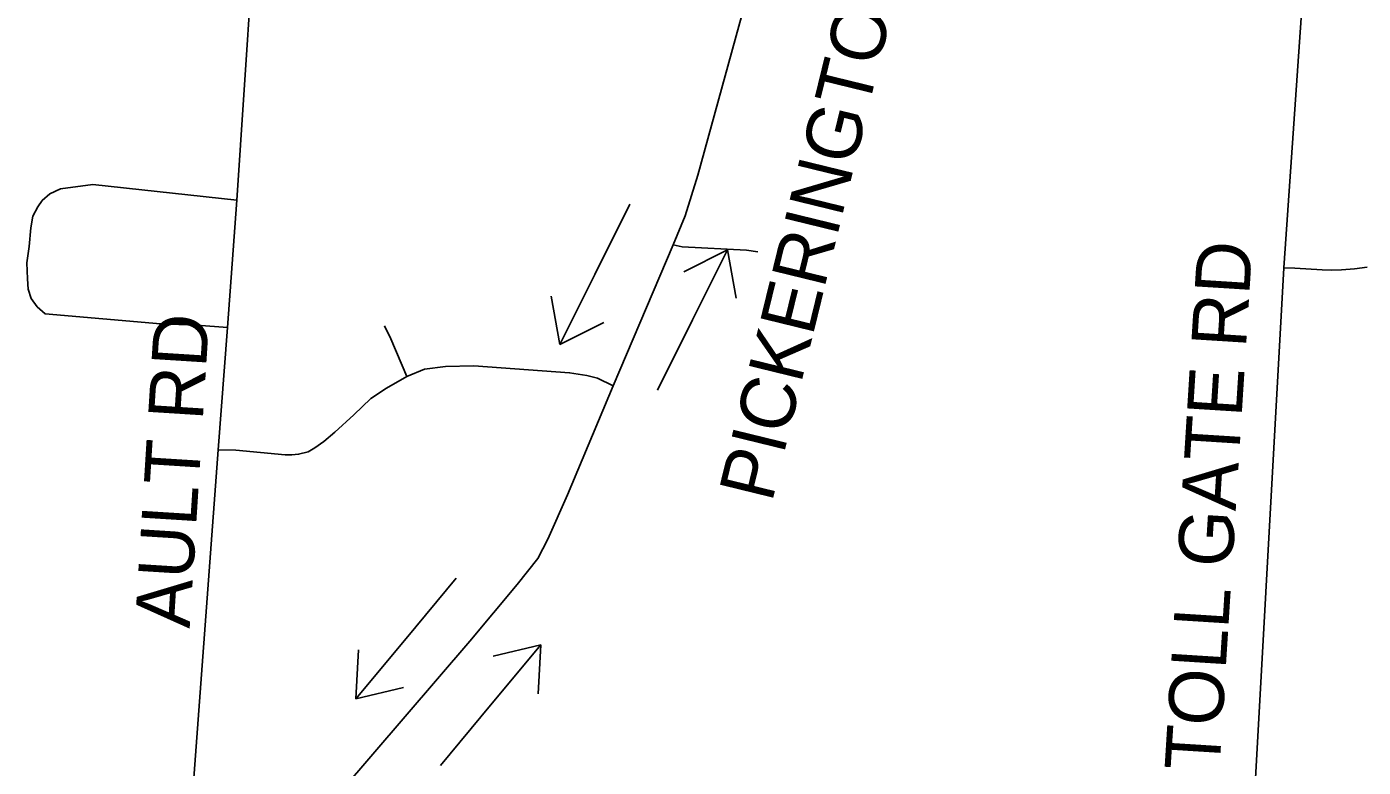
# Model space of a CAD drawing. Extents: x 1880545 to 1948545, y 79309 to 723051.
# Drawn here: x 1903722 to 1910544, y 696839 to 700619 of the extents above; entities that cross this region are included whole.
import ezdxf

# ---------------------------------------------------------------- set-up
doc = ezdxf.new("R2010")
doc.units = 0
for name, color, linetype in [('GM_X_County_Road', 7, 'Continuous'), ('GM_X_Township_Road', 7, 'Continuous'), ('SH_Text', 7, 'Continuous')]:
    doc.layers.add(name, color=color, linetype=linetype)

msp = doc.modelspace()

# ---------------------------------------------------------------- linework, layer by layer
at = {"layer": 'GM_X_County_Road'}
msp.add_lwpolyline([(1903743.6, 694852), (1904498.8, 695752), (1905984.5, 697482.2), (1906225.1, 697771.5), (1906330.5, 697904), (1906381.8, 698004.1), (1906482, 698229.9), (1906716.2, 698785.5), (1907022.1, 699505.3), (1907083, 699653.2), (1907147.2, 699860.4), (1907496.4, 701130), (1907579.5, 701447.1), (1907619.5, 701622.3), (1907630.8, 701703.2), (1907657.6, 701964), (1907699.4, 702415.6), (1907714.4, 702613)], dxfattribs=at)
at = {"layer": 'GM_X_Township_Road'}
for points in [[(1904498.8, 695752), (1904699.2, 698459.7), (1904747.1, 699083.9), (1904795.5, 699734.1), (1904909.4, 701450.1), (1904991.6, 702232.3), (1905034.1, 702803)], [(1909204, 694397.9), (1909237.3, 694606.7), (1909274.6, 694755.9), (1909351.4, 694905.3), (1909471.8, 695025), (1909703.6, 695238.2), (1909815.5, 695374.1), (1909874.1, 695504.6), (1909911.4, 695648.5), (1909954.1, 696077.5), (1910139.3, 699387.4), (1910347, 702406.2)], [(1903734.6, 699497.8), (1903743, 699591.9), (1903753.2, 699652), (1903779.5, 699699.9), (1903801.7, 699731.9), (1903839.9, 699765.8), (1903894.2, 699791.6), (1904059, 699813), (1904795.5, 699734.1)], [(1903734.6, 699497.8), (1903722.3, 699413.7), (1903726, 699331.6), (1903729.9, 699279.5), (1903745.7, 699231.3), (1903775.7, 699189.2), (1903815.6, 699152.9), (1904405.2, 699102.5), (1904589.7, 699095.8), (1904747.1, 699083.9)], [(1907022.1, 699505.3), (1907067.8, 699495.9), (1907396.8, 699478.5), (1907453.4, 699469.1)], [(1910139.3, 699387.4), (1910194.4, 699386), (1910334.6, 699377.2), (1910383.9, 699375.9), (1910433.1, 699377.5), (1910498.6, 699383.7), (1910563.9, 699390.9)], [(1905661.7, 698834.3), (1905581.5, 699025.7), (1905548.7, 699091.4)], [(1904699.2, 698459.7), (1904789.3, 698456.8), (1905042.1, 698434.2), (1905075.7, 698434), (1905109.9, 698436.9), (1905159.4, 698448.8), (1905193.3, 698469.6), (1905238.8, 698502.4), (1905295.3, 698549.8), (1905392, 698637.4), (1905479.4, 698721.2), (1905557.8, 698774.1), (1905661.7, 698834.3), (1905752.8, 698870.7), (1905860.4, 698885.3), (1906004.4, 698887.2), (1906492.9, 698852.5), (1906580.4, 698837.9), (1906635.1, 698825.2), (1906716.2, 698785.5)]]:
    msp.add_lwpolyline(points, dxfattribs=at)
at = {"layer": 'SH_Text'}
for p, q in [((1906801.1, 699712.6), (1906622.3, 699354.8)), ((1907298.9, 699479.7), (1907075.3, 699367.9)), ((1907120.1, 699121.9), (1907298.9, 699479.7)), ((1907298.9, 699479.7), (1907343.7, 699233.8)), ((1906622.3, 699354.8), (1906443.5, 698997)), ((1906443.5, 698997), (1906398.7, 699243)), ((1906443.5, 698997), (1906667.1, 699108.8)), ((1906941.3, 698764.1), (1907120.1, 699121.9)), ((1905914, 697803.9), (1905658.3, 697496.2)), ((1905658.3, 697496.2), (1905402.7, 697188.6)), ((1905402.7, 697188.6), (1905415.1, 697438.3)), ((1906089.9, 697156.1), (1906345.6, 697463.7)), ((1906345.6, 697463.7), (1906102.4, 697405.7)), ((1906345.6, 697463.7), (1906333.1, 697214)), ((1905402.7, 697188.6), (1905645.8, 697246.6)), ((1905834.3, 696848.4), (1906089.9, 697156.1))]:
    msp.add_line(p, q, dxfattribs=at)

# ---------------------------------------------------------------- texts
for s, height, rotation, p in [('PICKERINGTON RD NW', 279.999, 76.25875, (1907525.3, 698185)), ('TOLL GATE RD', 279.999, 86.40079, (1909809, 696815.8)), ('AULT RD', 280, 86.40079, (1904553.9, 697545.7))]:
    msp.add_text(s, height=height, rotation=rotation, dxfattribs=at).set_placement(p)

doc.saveas('drawing.dxf')
